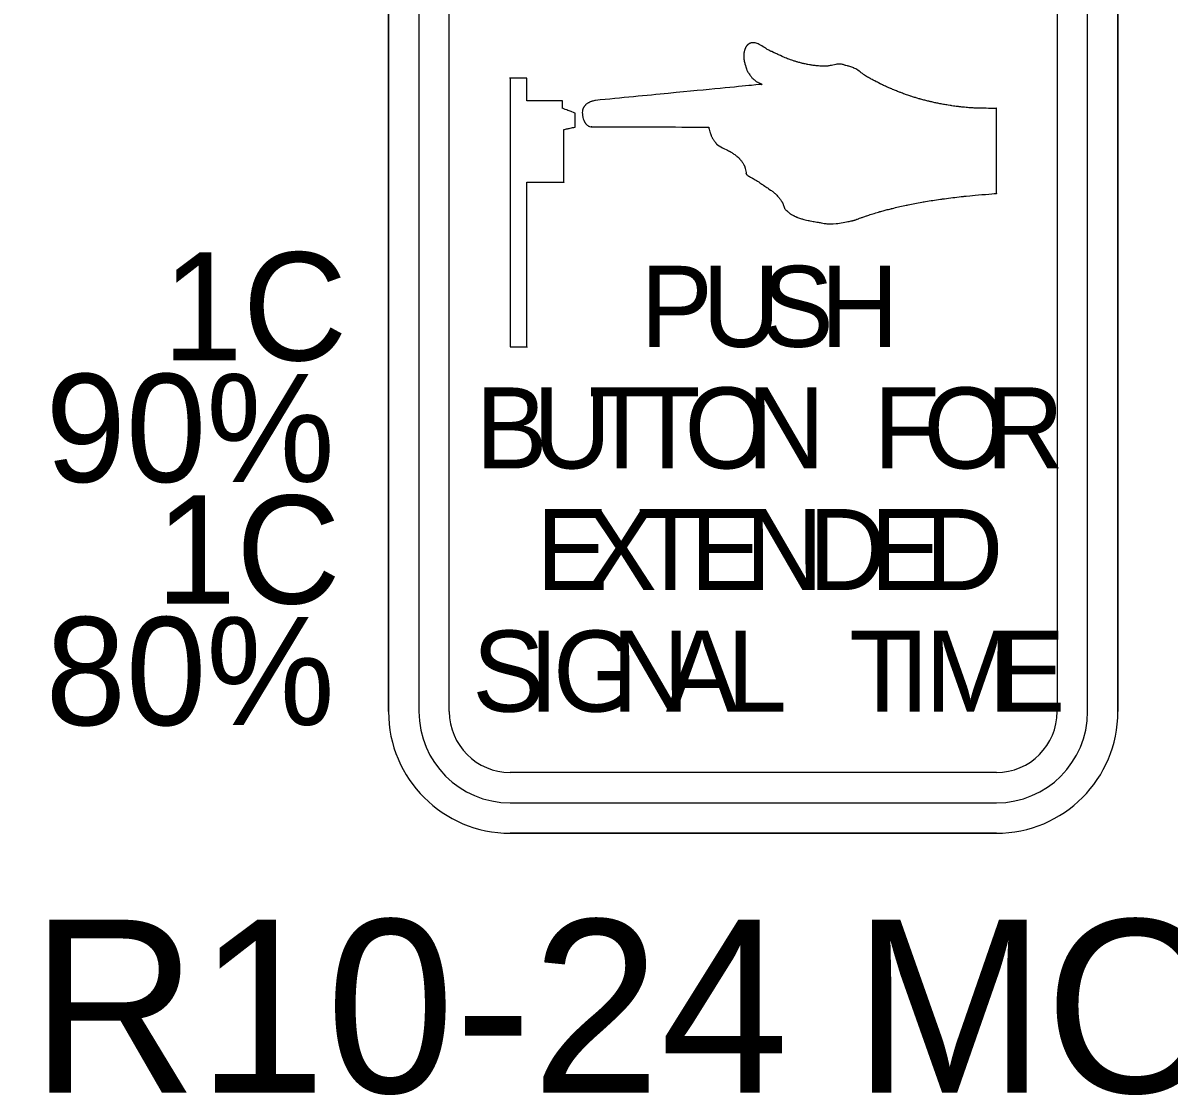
# Model space of a CAD drawing. Extents: x 99982 to 100176, y 99905 to 100011.
# Drawn here: x 100049.2714 to 100049.7487, y 99945.0774 to 99945.5238 of the extents above; entities that cross this region are included whole.
import ezdxf

# ---------------------------------------------------------------- set-up
doc = ezdxf.new("R2010")
doc.units = 0
doc.layers.add('TR_SN_ConstructionSigns', color=7, linetype='Continuous')

msp = doc.modelspace()

# ---------------------------------------------------------------- linework, layer by layer
at = {"layer": 'TR_SN_ConstructionSigns'}
for p, q in [((100049.42363, 99945.23704), (100049.42363, 99945.64204)), ((100049.42363, 99945.64204), (100049.42363, 99945.23704)), ((100049.42363, 99945.64204), (100049.42363, 99945.23704)), ((100049.43628, 99945.64204), (100049.43628, 99945.23704)), ((100049.44894, 99945.23704), (100049.44894, 99945.64204)), ((100049.70207, 99945.64204), (100049.70207, 99945.23704)), ((100049.71472, 99945.23704), (100049.71472, 99945.64204)), ((100049.72738, 99945.64204), (100049.72738, 99945.23704)), ((100049.72738, 99945.23704), (100049.72738, 99945.64204)), ((100049.72738, 99945.23704), (100049.72738, 99945.64204)), ((100049.67675, 99945.21173), (100049.47425, 99945.21173)), ((100049.47425, 99945.19907), (100049.67675, 99945.19907)), ((100049.67675, 99945.18641), (100049.47425, 99945.18641)), ((100049.47425, 99945.18641), (100049.67675, 99945.18641)), ((100049.47425, 99945.18641), (100049.67675, 99945.18641))]:
    msp.add_line(p, q, dxfattribs=at)
for centre, radius, start, end in [((100049.47425, 99945.23704), 0.05063, 180, 270), ((100049.47425, 99945.23704), 0.05063, 180, 270), ((100049.47425, 99945.23704), 0.05063, 180, 270), ((100049.47425, 99945.23704), 0.03797, 180, 270), ((100049.47425, 99945.23704), 0.02531, 180, 270), ((100049.67675, 99945.23704), 0.05063, 270, 0), ((100049.67675, 99945.23704), 0.05063, 270, 0), ((100049.67675, 99945.23704), 0.03797, 270, 0), ((100049.67675, 99945.23704), 0.02531, 270, 0), ((100049.67675, 99945.23704), 0.05063, 270, 0)]:
    msp.add_arc(centre, radius, start, end, dxfattribs=at)
for points, degree in [([(100049.57196, 99945.51252), (100049.57196, 99945.51252), (100049.57184, 99945.51216), (100049.57169, 99945.51168), (100049.57161, 99945.51109), (100049.57161, 99945.51109)], 3), ([(100049.57223, 99945.5133), (100049.57223, 99945.5133), (100049.57216, 99945.5131), (100049.57208, 99945.51288), (100049.57196, 99945.51252), (100049.57196, 99945.51252)], 3), ([(100049.5724, 99945.51369), (100049.5724, 99945.51369), (100049.57232, 99945.51353), (100049.57231, 99945.51349), (100049.57223, 99945.5133), (100049.57223, 99945.5133)], 3), ([(100049.5728, 99945.51427), (100049.5728, 99945.51427), (100049.57265, 99945.51408), (100049.57249, 99945.51386), (100049.5724, 99945.51369), (100049.5724, 99945.51369)], 3), ([(100049.57333, 99945.51481), (100049.57333, 99945.51481), (100049.57315, 99945.51466), (100049.57295, 99945.51446), (100049.5728, 99945.51427), (100049.5728, 99945.51427)], 3), ([(100049.57387, 99945.51516), (100049.57387, 99945.51516), (100049.5737, 99945.51507), (100049.57351, 99945.51496), (100049.57333, 99945.51481), (100049.57333, 99945.51481)], 3), ([(100049.57434, 99945.51535), (100049.57434, 99945.51535), (100049.5741, 99945.51527), (100049.57404, 99945.51524), (100049.57387, 99945.51516), (100049.57387, 99945.51516)], 3), ([(100049.57635, 99945.51548), (100049.57635, 99945.51548), (100049.57536, 99945.51564), (100049.57458, 99945.51543), (100049.57434, 99945.51535), (100049.57434, 99945.51535)], 3), ([(100049.58098, 99945.51302), (100049.58098, 99945.51302), (100049.57973, 99945.5138), (100049.57734, 99945.51531), (100049.57635, 99945.51548), (100049.57635, 99945.51548)], 3), ([(100049.58421, 99945.51137), (100049.58421, 99945.51137), (100049.58305, 99945.51191), (100049.58224, 99945.51224), (100049.58098, 99945.51302), (100049.58098, 99945.51302)], 3), ([(100049.57161, 99945.51109), (100049.57161, 99945.51109), (100049.57152, 99945.51049), (100049.57152, 99945.50963), (100049.5716, 99945.50894), (100049.5716, 99945.50894)], 3), ([(100049.5716, 99945.50894), (100049.5716, 99945.50894), (100049.57168, 99945.50825), (100049.57188, 99945.50737), (100049.57198, 99945.50697), (100049.57198, 99945.50697)], 3), ([(100049.58787, 99945.50971), (100049.58787, 99945.50971), (100049.58679, 99945.51017), (100049.58537, 99945.51084), (100049.58421, 99945.51137), (100049.58421, 99945.51137)], 3), ([(100049.59068, 99945.50859), (100049.59068, 99945.50859), (100049.5897, 99945.50895), (100049.58895, 99945.50925), (100049.58787, 99945.50971), (100049.58787, 99945.50971)], 3), ([(100049.59377, 99945.50756), (100049.59377, 99945.50756), (100049.59292, 99945.50782), (100049.59166, 99945.50823), (100049.59068, 99945.50859), (100049.59068, 99945.50859)], 3), ([(100049.59576, 99945.50701), (100049.59576, 99945.50701), (100049.59506, 99945.50719), (100049.59462, 99945.50731), (100049.59377, 99945.50756), (100049.59377, 99945.50756)], 3), ([(100049.57198, 99945.50697), (100049.57198, 99945.50697), (100049.57208, 99945.50657), (100049.57211, 99945.50648), (100049.57221, 99945.50617), (100049.57221, 99945.50617)], 3), ([(100049.57221, 99945.50617), (100049.57221, 99945.50617), (100049.5723, 99945.50586), (100049.57246, 99945.50546), (100049.57257, 99945.50511), (100049.57257, 99945.50511)], 3), ([(100049.57257, 99945.50511), (100049.57257, 99945.50511), (100049.57268, 99945.50476), (100049.57269, 99945.50458), (100049.57289, 99945.50408), (100049.57289, 99945.50408)], 3), ([(100049.57289, 99945.50408), (100049.57289, 99945.50408), (100049.57309, 99945.50357), (100049.57384, 99945.50252), (100049.57424, 99945.50195), (100049.57424, 99945.50195)], 3), ([(100049.59799, 99945.50653), (100049.59799, 99945.50653), (100049.597, 99945.50672), (100049.59647, 99945.50684), (100049.59576, 99945.50701), (100049.59576, 99945.50701)], 3), ([(100049.60176, 99945.50597), (100049.60176, 99945.50597), (100049.60025, 99945.50614), (100049.59899, 99945.50635), (100049.59799, 99945.50653), (100049.59799, 99945.50653)], 3), ([(100049.60704, 99945.50592), (100049.60704, 99945.50592), (100049.60536, 99945.50565), (100049.60326, 99945.50579), (100049.60176, 99945.50597), (100049.60176, 99945.50597)], 3), ([(100049.61195, 99945.50661), (100049.61195, 99945.50661), (100049.61098, 99945.50674), (100049.60873, 99945.5062), (100049.60704, 99945.50592), (100049.60704, 99945.50592)], 3), ([(100049.61384, 99945.50612), (100049.61384, 99945.50612), (100049.61295, 99945.50638), (100049.61292, 99945.50648), (100049.61195, 99945.50661), (100049.61195, 99945.50661)], 3), ([(100049.61732, 99945.50507), (100049.61732, 99945.50507), (100049.61594, 99945.50568), (100049.61474, 99945.50586), (100049.61384, 99945.50612), (100049.61384, 99945.50612)], 3), ([(100049.62181, 99945.50207), (100049.62181, 99945.50207), (100049.62044, 99945.50301), (100049.6187, 99945.50447), (100049.61732, 99945.50507), (100049.61732, 99945.50507)], 3), ([(100049.47425, 99945.50079), (100049.47425, 99945.50079), (100049.47425, 99945.50079), (100049.47425, 99945.38891)], 2), ([(100049.48122, 99945.50079), (100049.48122, 99945.50079), (100049.48122, 99945.50079), (100049.47425, 99945.50079)], 2), ([(100049.48122, 99945.49134), (100049.48122, 99945.49134), (100049.48122, 99945.49134), (100049.48122, 99945.50079)], 2), ([(100049.57905, 99945.49821), (100049.57905, 99945.49821), (100049.57905, 99945.49821), (100049.50981, 99945.49152)], 2), ([(100049.57424, 99945.50195), (100049.57424, 99945.50195), (100049.57465, 99945.50138), (100049.5749, 99945.50098), (100049.57526, 99945.50064), (100049.57526, 99945.50064)], 3), ([(100049.57526, 99945.50064), (100049.57526, 99945.50064), (100049.57562, 99945.5003), (100049.57596, 99945.5001), (100049.5763, 99945.49983), (100049.5763, 99945.49983)], 3), ([(100049.5763, 99945.49983), (100049.5763, 99945.49983), (100049.57664, 99945.49955), (100049.57687, 99945.49927), (100049.57738, 99945.49909), (100049.57738, 99945.49909)], 3), ([(100049.57738, 99945.49909), (100049.57738, 99945.49909), (100049.57789, 99945.49891), (100049.57913, 99945.49835), (100049.57913, 99945.4983), (100049.57913, 99945.4983)], 3), ([(100049.57913, 99945.49821), (100049.57913, 99945.49821), (100049.57913, 99945.49818), (100049.57905, 99945.49821), (100049.57905, 99945.49821)], 3), ([(100049.57913, 99945.4983), (100049.57913, 99945.4983), (100049.57913, 99945.49826), (100049.57913, 99945.49824), (100049.57913, 99945.49821), (100049.57913, 99945.49821)], 3), ([(100049.62576, 99945.49983), (100049.62576, 99945.49983), (100049.62461, 99945.50043), (100049.62318, 99945.50114), (100049.62181, 99945.50207), (100049.62181, 99945.50207)], 3), ([(100049.62865, 99945.49833), (100049.62865, 99945.49833), (100049.6275, 99945.4989), (100049.62692, 99945.49923), (100049.62576, 99945.49983), (100049.62576, 99945.49983)], 3), ([(100049.63274, 99945.49647), (100049.63274, 99945.49647), (100049.63137, 99945.49705), (100049.62981, 99945.49775), (100049.62865, 99945.49833), (100049.62865, 99945.49833)], 3), ([(100049.63683, 99945.49481), (100049.63683, 99945.49481), (100049.63544, 99945.49533), (100049.6341, 99945.49588), (100049.63274, 99945.49647), (100049.63274, 99945.49647)], 3), ([(100049.64108, 99945.49331), (100049.64108, 99945.49331), (100049.63973, 99945.49375), (100049.63822, 99945.49428), (100049.63683, 99945.49481), (100049.63683, 99945.49481)], 3), ([(100049.64492, 99945.49214), (100049.64492, 99945.49214), (100049.6436, 99945.49251), (100049.64243, 99945.49287), (100049.64108, 99945.49331), (100049.64108, 99945.49331)], 3), ([(100049.49601, 99945.49134), (100049.49601, 99945.49134), (100049.49601, 99945.49134), (100049.48122, 99945.49134)], 2), ([(100049.49601, 99945.4882), (100049.49601, 99945.4882), (100049.49601, 99945.4882), (100049.49601, 99945.49134)], 2), ([(100049.49604, 99945.48826), (100049.49604, 99945.48826), (100049.49604, 99945.48826), (100049.49601, 99945.4882)], 2), ([(100049.49604, 99945.48826), (100049.49604, 99945.48826), (100049.49604, 99945.48826), (100049.49601, 99945.4882)], 2), ([(100049.50132, 99945.48619), (100049.50132, 99945.48619), (100049.50132, 99945.48619), (100049.49604, 99945.48826)], 2), ([(100049.50478, 99945.48848), (100049.50478, 99945.48848), (100049.50466, 99945.48827), (100049.50456, 99945.48807), (100049.50444, 99945.48763), (100049.50444, 99945.48763)], 3), ([(100049.50507, 99945.48893), (100049.50507, 99945.48893), (100049.50492, 99945.48872), (100049.5049, 99945.48869), (100049.50478, 99945.48848), (100049.50478, 99945.48848)], 3), ([(100049.5057, 99945.48968), (100049.5057, 99945.48968), (100049.50544, 99945.48943), (100049.50522, 99945.48914), (100049.50507, 99945.48893), (100049.50507, 99945.48893)], 3), ([(100049.50667, 99945.49041), (100049.50667, 99945.49041), (100049.50633, 99945.49021), (100049.50596, 99945.48994), (100049.5057, 99945.48968), (100049.5057, 99945.48968)], 3), ([(100049.50769, 99945.49091), (100049.50769, 99945.49091), (100049.50735, 99945.49078), (100049.507, 99945.49061), (100049.50667, 99945.49041), (100049.50667, 99945.49041)], 3), ([(100049.50865, 99945.49125), (100049.50865, 99945.49125), (100049.50833, 99945.49115), (100049.50802, 99945.49105), (100049.50769, 99945.49091), (100049.50769, 99945.49091)], 3), ([(100049.50981, 99945.49152), (100049.50981, 99945.49152), (100049.50981, 99945.49152), (100049.50897, 99945.49136), (100049.50865, 99945.49125)], 3), ([(100049.64902, 99945.49107), (100049.64902, 99945.49107), (100049.64763, 99945.49141), (100049.64625, 99945.49176), (100049.64492, 99945.49214), (100049.64492, 99945.49214)], 3), ([(100049.65329, 99945.49014), (100049.65329, 99945.49014), (100049.65182, 99945.49043), (100049.65042, 99945.49074), (100049.64902, 99945.49107), (100049.64902, 99945.49107)], 3), ([(100049.65787, 99945.48935), (100049.65787, 99945.48935), (100049.65659, 99945.48955), (100049.65477, 99945.48985), (100049.65329, 99945.49014), (100049.65329, 99945.49014)], 3), ([(100049.66091, 99945.48893), (100049.66091, 99945.48893), (100049.65981, 99945.48907), (100049.65914, 99945.48916), (100049.65787, 99945.48935), (100049.65787, 99945.48935)], 3), ([(100049.66444, 99945.48856), (100049.66444, 99945.48856), (100049.66342, 99945.48865), (100049.662, 99945.48879), (100049.66091, 99945.48893), (100049.66091, 99945.48893)], 3), ([(100049.66702, 99945.48837), (100049.66702, 99945.48837), (100049.66616, 99945.48843), (100049.66546, 99945.48848), (100049.66444, 99945.48856), (100049.66444, 99945.48856)], 3), ([(100049.67661, 99945.48816), (100049.67661, 99945.48816), (100049.67661, 99945.48816), (100049.66788, 99945.48831), (100049.66702, 99945.48837)], 3), ([(100049.67675, 99945.48834), (100049.67675, 99945.48834), (100049.67675, 99945.48834), (100049.67661, 99945.48816)], 2), ([(100049.67675, 99945.45279), (100049.67675, 99945.45279), (100049.67675, 99945.45279), (100049.67675, 99945.48834)], 2), ([(100049.50139, 99945.48044), (100049.50139, 99945.48044), (100049.50139, 99945.48044), (100049.50132, 99945.48619)], 2), ([(100049.50444, 99945.48763), (100049.50444, 99945.48763), (100049.50433, 99945.48718), (100049.5043, 99945.48579), (100049.50443, 99945.48505), (100049.50443, 99945.48505)], 3), ([(100049.50443, 99945.48505), (100049.50443, 99945.48505), (100049.50455, 99945.48431), (100049.50481, 99945.4835), (100049.50494, 99945.4832), (100049.50494, 99945.4832)], 3), ([(100049.49658, 99945.47936), (100049.49658, 99945.47936), (100049.49658, 99945.47936), (100049.50139, 99945.48044)], 2), ([(100049.49659, 99945.45744), (100049.49659, 99945.45744), (100049.49659, 99945.45744), (100049.49658, 99945.47936)], 2), ([(100049.50494, 99945.4832), (100049.50494, 99945.4832), (100049.50507, 99945.48291), (100049.50511, 99945.48283), (100049.50522, 99945.48263), (100049.50522, 99945.48263)], 3), ([(100049.50522, 99945.48263), (100049.50522, 99945.48263), (100049.50532, 99945.48243), (100049.50546, 99945.48217), (100049.50559, 99945.482), (100049.50559, 99945.482)], 3), ([(100049.50559, 99945.482), (100049.50559, 99945.482), (100049.50572, 99945.48183), (100049.50577, 99945.48178), (100049.50597, 99945.48159), (100049.50597, 99945.48159)], 3), ([(100049.50597, 99945.48159), (100049.50597, 99945.48159), (100049.50618, 99945.48141), (100049.50654, 99945.48113), (100049.50684, 99945.48092), (100049.50684, 99945.48092)], 3), ([(100049.50684, 99945.48092), (100049.50684, 99945.48092), (100049.50714, 99945.48071), (100049.5082, 99945.48051), (100049.5082, 99945.48051)], 3), ([(100049.5082, 99945.48051), (100049.5082, 99945.48051), (100049.5082, 99945.48051), (100049.55695, 99945.48044)], 2), ([(100049.55695, 99945.48044), (100049.55695, 99945.48044), (100049.55695, 99945.48044), (100049.55741, 99945.47844), (100049.55753, 99945.4781)], 3), ([(100049.55753, 99945.4781), (100049.55753, 99945.4781), (100049.55765, 99945.47777), (100049.55776, 99945.47744), (100049.5579, 99945.4771), (100049.5579, 99945.4771)], 3), ([(100049.5579, 99945.4771), (100049.5579, 99945.4771), (100049.55804, 99945.47675), (100049.55822, 99945.47637), (100049.5584, 99945.47603), (100049.5584, 99945.47603)], 3), ([(100049.5584, 99945.47603), (100049.5584, 99945.47603), (100049.55859, 99945.47569), (100049.55874, 99945.47545), (100049.559, 99945.47507), (100049.559, 99945.47507)], 3), ([(100049.559, 99945.47507), (100049.559, 99945.47507), (100049.55926, 99945.47469), (100049.55971, 99945.47407), (100049.55995, 99945.47375), (100049.55995, 99945.47375)], 3), ([(100049.55995, 99945.47375), (100049.55995, 99945.47375), (100049.56018, 99945.47342), (100049.56017, 99945.47341), (100049.56044, 99945.47311), (100049.56044, 99945.47311)], 3), ([(100049.56044, 99945.47311), (100049.56044, 99945.47311), (100049.5607, 99945.47281), (100049.56467, 99945.47083), (100049.56558, 99945.47037), (100049.56558, 99945.47037)], 3), ([(100049.56558, 99945.47037), (100049.56558, 99945.47037), (100049.56648, 99945.4699), (100049.56678, 99945.46966), (100049.5673, 99945.46929), (100049.5673, 99945.46929)], 3), ([(100049.5673, 99945.46929), (100049.5673, 99945.46929), (100049.56782, 99945.46892), (100049.56835, 99945.4685), (100049.56873, 99945.46821), (100049.56873, 99945.46821)], 3), ([(100049.56873, 99945.46821), (100049.56873, 99945.46821), (100049.5691, 99945.46792), (100049.5693, 99945.46776), (100049.56953, 99945.46754), (100049.56953, 99945.46754)], 3), ([(100049.56953, 99945.46754), (100049.56953, 99945.46754), (100049.56977, 99945.46731), (100049.5699, 99945.46716), (100049.57015, 99945.46685), (100049.57015, 99945.46685)], 3), ([(100049.57015, 99945.46685), (100049.57015, 99945.46685), (100049.5704, 99945.46655), (100049.57076, 99945.4661), (100049.57103, 99945.4657), (100049.57103, 99945.4657)], 3), ([(100049.57103, 99945.4657), (100049.57103, 99945.4657), (100049.57131, 99945.4653), (100049.57164, 99945.46471), (100049.57175, 99945.46444), (100049.57175, 99945.46444)], 3), ([(100049.57175, 99945.46444), (100049.57175, 99945.46444), (100049.57187, 99945.46418), (100049.57189, 99945.46411), (100049.57196, 99945.46391), (100049.57196, 99945.46391)], 3), ([(100049.57196, 99945.46391), (100049.57196, 99945.46391), (100049.57203, 99945.46371), (100049.5721, 99945.46347), (100049.57217, 99945.46325), (100049.57217, 99945.46325)], 3), ([(100049.57217, 99945.46325), (100049.57217, 99945.46325), (100049.57224, 99945.46303), (100049.57262, 99945.46097), (100049.57262, 99945.46097)], 3), ([(100049.57262, 99945.46097), (100049.57262, 99945.46097), (100049.57262, 99945.46097), (100049.57239, 99945.46123), (100049.57244, 99945.46114)], 3), ([(100049.57244, 99945.46114), (100049.57244, 99945.46114), (100049.57249, 99945.46105), (100049.57251, 99945.461), (100049.5726, 99945.46087), (100049.5726, 99945.46087)], 3), ([(100049.5726, 99945.46087), (100049.5726, 99945.46087), (100049.57268, 99945.46073), (100049.57385, 99945.45979), (100049.57507, 99945.4592), (100049.57507, 99945.4592)], 3), ([(100049.48122, 99945.45744), (100049.48122, 99945.45744), (100049.48122, 99945.45744), (100049.49659, 99945.45744)], 2), ([(100049.48122, 99945.38891), (100049.48122, 99945.38891), (100049.48122, 99945.38891), (100049.48122, 99945.45744)], 2), ([(100049.57507, 99945.4592), (100049.57507, 99945.4592), (100049.57629, 99945.4586), (100049.57832, 99945.45721), (100049.57944, 99945.45644), (100049.57944, 99945.45644)], 3), ([(100049.57944, 99945.45644), (100049.57944, 99945.45644), (100049.58055, 99945.45567), (100049.58102, 99945.45537), (100049.58191, 99945.45477), (100049.58191, 99945.45477)], 3), ([(100049.58191, 99945.45477), (100049.58191, 99945.45477), (100049.58279, 99945.45418), (100049.5839, 99945.4534), (100049.58464, 99945.45271), (100049.58464, 99945.45271)], 3), ([(100049.58464, 99945.45271), (100049.58464, 99945.45271), (100049.58538, 99945.45202), (100049.58595, 99945.45131), (100049.5864, 99945.45073), (100049.5864, 99945.45073)], 3), ([(100049.5864, 99945.45073), (100049.5864, 99945.45073), (100049.58686, 99945.45015), (100049.58718, 99945.4497), (100049.58744, 99945.44929), (100049.58744, 99945.44929)], 3), ([(100049.64651, 99945.44928), (100049.64651, 99945.44928), (100049.649, 99945.44972), (100049.65153, 99945.45012), (100049.65429, 99945.4505), (100049.65429, 99945.4505)], 3), ([(100049.65429, 99945.4505), (100049.65429, 99945.4505), (100049.65704, 99945.45088), (100049.66012, 99945.45124), (100049.66304, 99945.45158), (100049.66304, 99945.45158)], 3), ([(100049.66304, 99945.45158), (100049.66304, 99945.45158), (100049.66596, 99945.45192), (100049.67675, 99945.45279), (100049.67675, 99945.45279)], 3), ([(100049.58744, 99945.44929), (100049.58744, 99945.44929), (100049.5877, 99945.44889), (100049.58779, 99945.44875), (100049.58796, 99945.44829), (100049.58796, 99945.44829)], 3), ([(100049.58796, 99945.44829), (100049.58796, 99945.44829), (100049.58814, 99945.44783), (100049.58828, 99945.44706), (100049.58857, 99945.44657), (100049.58857, 99945.44657)], 3), ([(100049.58857, 99945.44657), (100049.58857, 99945.44657), (100049.58886, 99945.44607), (100049.58932, 99945.44571), (100049.58968, 99945.44539), (100049.58968, 99945.44539)], 3), ([(100049.58968, 99945.44539), (100049.58968, 99945.44539), (100049.59005, 99945.44507), (100049.59025, 99945.44486), (100049.59066, 99945.44456), (100049.59066, 99945.44456)], 3), ([(100049.62274, 99945.4435), (100049.62274, 99945.4435), (100049.62417, 99945.44398), (100049.62644, 99945.44469), (100049.62814, 99945.44517), (100049.62814, 99945.44517)], 3), ([(100049.62814, 99945.44517), (100049.62814, 99945.44517), (100049.62983, 99945.44566), (100049.63104, 99945.44598), (100049.6329, 99945.44644), (100049.6329, 99945.44644)], 3), ([(100049.6329, 99945.44644), (100049.6329, 99945.44644), (100049.63477, 99945.4469), (100049.63708, 99945.44744), (100049.63935, 99945.44791), (100049.63935, 99945.44791)], 3), ([(100049.63935, 99945.44791), (100049.63935, 99945.44791), (100049.64162, 99945.44839), (100049.64402, 99945.44885), (100049.64651, 99945.44928), (100049.64651, 99945.44928)], 3), ([(100049.59066, 99945.44456), (100049.59066, 99945.44456), (100049.59107, 99945.44425), (100049.59167, 99945.4439), (100049.59219, 99945.44363), (100049.59219, 99945.44363)], 3), ([(100049.59219, 99945.44363), (100049.59219, 99945.44363), (100049.59272, 99945.44336), (100049.59316, 99945.44316), (100049.59378, 99945.44291), (100049.59378, 99945.44291)], 3), ([(100049.59378, 99945.44291), (100049.59378, 99945.44291), (100049.59439, 99945.44267), (100049.59507, 99945.44244), (100049.59589, 99945.4422), (100049.59589, 99945.4422)], 3), ([(100049.59589, 99945.4422), (100049.59589, 99945.4422), (100049.59671, 99945.44196), (100049.59744, 99945.44176), (100049.59868, 99945.44149), (100049.59868, 99945.44149)], 3), ([(100049.59868, 99945.44149), (100049.59868, 99945.44149), (100049.59993, 99945.44122), (100049.60193, 99945.44088), (100049.60337, 99945.44065), (100049.60337, 99945.44065)], 3), ([(100049.60337, 99945.44065), (100049.60337, 99945.44065), (100049.6048, 99945.44041), (100049.60531, 99945.44025), (100049.60729, 99945.44013), (100049.60729, 99945.44013)], 3), ([(100049.60729, 99945.44013), (100049.60729, 99945.44013), (100049.60927, 99945.44), (100049.61658, 99945.44136), (100049.6171, 99945.44151), (100049.6171, 99945.44151)], 3), ([(100049.6171, 99945.44151), (100049.6171, 99945.44151), (100049.61761, 99945.44166), (100049.61771, 99945.44169), (100049.61812, 99945.44183), (100049.61812, 99945.44183)], 3), ([(100049.61812, 99945.44183), (100049.61812, 99945.44183), (100049.61853, 99945.44197), (100049.61883, 99945.44209), (100049.61954, 99945.44236), (100049.61954, 99945.44236)], 3), ([(100049.61954, 99945.44236), (100049.61954, 99945.44236), (100049.62025, 99945.44263), (100049.62131, 99945.44302), (100049.62274, 99945.4435), (100049.62274, 99945.4435)], 3), ([(100049.47425, 99945.38891), (100049.47425, 99945.38891), (100049.47425, 99945.38891), (100049.48122, 99945.38891)], 2)]:
    msp.add_open_spline(points, degree=degree, dxfattribs=at)

# ---------------------------------------------------------------- texts
for s, height, p in [('1C', 0.045, (100049.32943, 99945.38329)), ('P', 0.03375, (100049.52857, 99945.38891)), ('U', 0.03375, (100049.55424, 99945.38891)), ('S', 0.03375, (100049.57888, 99945.38891)), ('H', 0.03375, (100049.60353, 99945.38891)), ('1C, 90%', 0.045, (100049.17043, 99945.33266)), ('B', 0.03375, (100049.45976, 99945.33829)), ('U', 0.03375, (100049.48382, 99945.33829)), ('T', 0.03375, (100049.50697, 99945.33829)), ('T', 0.03375, (100049.52601, 99945.33829)), ('O', 0.03375, (100049.54687, 99945.33829)), ('N', 0.03375, (100049.57285, 99945.33829)), ('F', 0.03375, (100049.6255, 99945.33829)), ('O', 0.03375, (100049.64636, 99945.33829)), ('R', 0.03375, (100049.67235, 99945.33829)), ('1C', 0.045, (100049.32672, 99945.28204)), ('E', 0.03375, (100049.48505, 99945.28766)), ('X', 0.03375, (100049.5053, 99945.28766)), ('T', 0.03375, (100049.52724, 99945.28766)), ('E', 0.03375, (100049.54918, 99945.28766)), ('N', 0.03375, (100049.57213, 99945.28766)), ('D', 0.03375, (100049.59845, 99945.28766)), ('E', 0.03375, (100049.6241, 99945.28766)), ('D', 0.03375, (100049.64705, 99945.28766)), ('1C, 80%', 0.045, (100049.17043, 99945.23141)), ('S', 0.03375, (100049.45849, 99945.23704)), ('I', 0.03375, (100049.48198, 99945.23704)), ('G', 0.03375, (100049.49211, 99945.23704)), ('N', 0.03375, (100049.51641, 99945.23704)), ('A', 0.03375, (100049.53909, 99945.23704)), ('L', 0.03375, (100049.56447, 99945.23704)), ('T', 0.03375, (100049.61543, 99945.23704)), ('I', 0.03375, (100049.63642, 99945.23704)), ('M', 0.03375, (100049.64709, 99945.23704)), ('E', 0.03375, (100049.6753, 99945.23704))]:
    msp.add_text(s, height=height, dxfattribs=at).set_placement(p)
msp.add_text('R10-24 MOD', height=0.072, rotation=360, dxfattribs=at).set_placement((100049.27452, 99945.07841))

doc.saveas('drawing.dxf')
